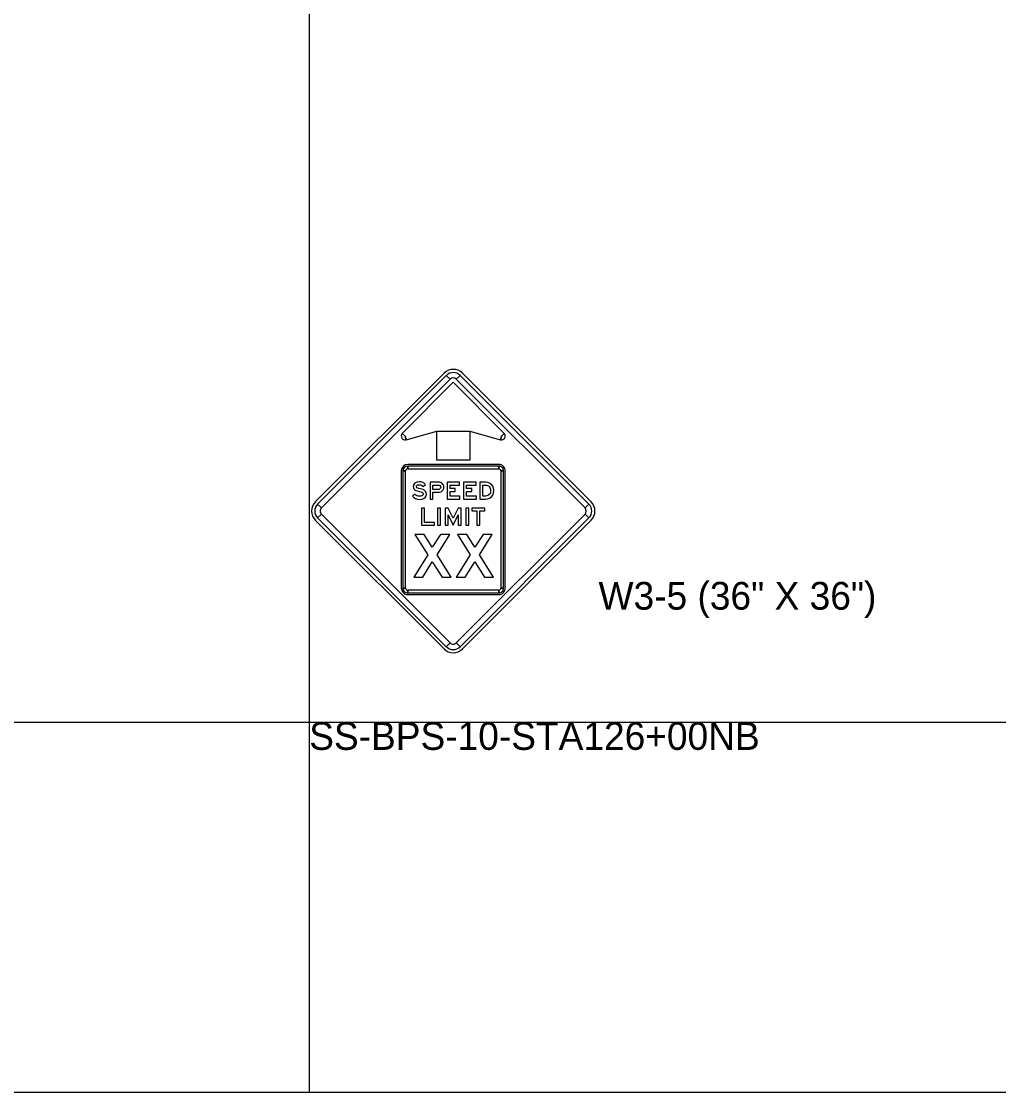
# Model space of a CAD drawing. Extents: x 1001568 to 1002149, y 1840825 to 1841423.
# Drawn here: x 1001900.5 to 1001914.59, y 1841048.13 to 1841063.57 of the extents above; entities that cross this region are included whole.
import ezdxf

# ---------------------------------------------------------------- set-up
doc = ezdxf.new("R2010")
doc.units = 0
for name, color, linetype in [('40', 7, 'Continuous'), ('R_No Plot', 7, 'Continuous'), ('SIGNS', 7, 'Continuous')]:
    doc.layers.add(name, color=color, linetype=linetype)

msp = doc.modelspace()

# ---------------------------------------------------------------- linework, layer by layer
at = {"layer": 'R_No Plot'}
for p, q in [((1001904.65, 1841110.667), (1001904.65, 1841048.127)), ((1001890.65, 1841053.469), (1001982.133, 1841053.469))]:
    msp.add_line(p, q, dxfattribs=at)
msp.add_lwpolyline([(1001886.411, 1841110.667), (1001964.232, 1841110.667), (1001964.232, 1841107.694), (1001968.454, 1841107.694), (1001968.454, 1841106.882), (1001982.133, 1841106.882), (1001982.133, 1841048.127), (1001886.411, 1841048.127)], close=True, dxfattribs=at)
at = {"layer": 'SIGNS'}
for p, q in [((1001906.594, 1841058.502), (1001904.738, 1841056.645)), ((1001906.627, 1841058.468), (1001906.683, 1841058.413)), ((1001906.771, 1841058.413), (1001906.826, 1841058.468)), ((1001908.716, 1841056.645), (1001906.859, 1841058.502)), ((1001906.032, 1841057.594), (1001905.992, 1841057.632)), ((1001906.046, 1841057.541), (1001906.032, 1841057.594)), ((1001907.422, 1841057.594), (1001907.408, 1841057.541)), ((1001907.462, 1841057.632), (1001907.422, 1841057.594)), ((1001905.977, 1841057.091), (1001905.977, 1841055.403)), ((1001906, 1841057.091), (1001906.039, 1841057.091)), ((1001907.383, 1841057.185), (1001906.071, 1841057.185)), ((1001906.071, 1841057.122), (1001906.071, 1841057.161)), ((1001907.383, 1841057.161), (1001907.383, 1841057.122)), ((1001907.414, 1841057.091), (1001907.453, 1841057.091)), ((1001907.477, 1841055.403), (1001907.477, 1841057.091)), ((1001904.827, 1841056.557), (1001904.771, 1841056.612)), ((1001908.682, 1841056.612), (1001908.627, 1841056.557)), ((1001904.771, 1841056.413), (1001904.827, 1841056.469)), ((1001908.627, 1841056.469), (1001908.682, 1841056.413)), ((1001904.738, 1841056.38), (1001906.594, 1841054.524)), ((1001906.859, 1841054.524), (1001908.716, 1841056.38)), ((1001906.039, 1841055.403), (1001906, 1841055.403)), ((1001906.071, 1841055.333), (1001906.071, 1841055.372)), ((1001907.383, 1841055.372), (1001907.383, 1841055.333)), ((1001907.453, 1841055.403), (1001907.414, 1841055.403)), ((1001906.071, 1841055.31), (1001907.383, 1841055.31)), ((1001906.683, 1841054.612), (1001906.627, 1841054.557)), ((1001906.826, 1841054.557), (1001906.771, 1841054.612))]:
    msp.add_line(p, q, dxfattribs=at)
for points in [[(1001906.627, 1841058.468), (1001904.771, 1841056.612), (1001904.827, 1841056.557), (1001906.683, 1841058.413), (1001906.627, 1841058.468), (1001906.627, 1841058.468)], [(1001908.682, 1841056.612), (1001906.826, 1841058.468), (1001906.771, 1841058.413), (1001908.627, 1841056.557), (1001908.682, 1841056.612), (1001908.682, 1841056.612)], [(1001906.727, 1841058.372), (1001905.992, 1841057.632), (1001906.032, 1841057.594), (1001906.046, 1841057.541), (1001906.489, 1841057.664), (1001906.965, 1841057.664), (1001907.408, 1841057.541), (1001907.422, 1841057.594), (1001907.462, 1841057.632), (1001906.727, 1841058.372), (1001906.727, 1841058.372)], [(1001906.965, 1841057.247), (1001906.489, 1841057.247), (1001906.489, 1841057.664), (1001906.965, 1841057.664), (1001906.965, 1841057.247), (1001906.965, 1841057.247)], [(1001906, 1841057.091), (1001906, 1841055.403), (1001906.039, 1841055.403), (1001906.039, 1841057.091), (1001906, 1841057.091), (1001906, 1841057.091)], [(1001907.383, 1841057.161), (1001906.071, 1841057.161), (1001906.071, 1841057.122), (1001907.383, 1841057.122), (1001907.383, 1841057.161), (1001907.383, 1841057.161)], [(1001907.453, 1841055.403), (1001907.453, 1841057.091), (1001907.414, 1841057.091), (1001907.414, 1841055.403), (1001907.453, 1841055.403), (1001907.453, 1841055.403)], [(1001906.139, 1841056.729), (1001906.161, 1841056.707), (1001906.185, 1841056.692), (1001906.212, 1841056.683), (1001906.242, 1841056.68), (1001906.277, 1841056.684), (1001906.307, 1841056.698), (1001906.321, 1841056.709), (1001906.331, 1841056.722), (1001906.338, 1841056.737), (1001906.34, 1841056.753), (1001906.337, 1841056.774), (1001906.33, 1841056.792), (1001906.318, 1841056.806), (1001906.302, 1841056.818), (1001906.278, 1841056.827), (1001906.232, 1841056.839), (1001906.216, 1841056.844), (1001906.204, 1841056.85), (1001906.197, 1841056.857), (1001906.195, 1841056.866), (1001906.197, 1841056.877), (1001906.205, 1841056.885), (1001906.218, 1841056.889), (1001906.236, 1841056.891), (1001906.253, 1841056.889), (1001906.268, 1841056.885), (1001906.282, 1841056.877), (1001906.295, 1841056.867), (1001906.329, 1841056.896), (1001906.309, 1841056.913), (1001906.287, 1841056.925), (1001906.264, 1841056.932), (1001906.238, 1841056.935), (1001906.205, 1841056.931), (1001906.178, 1841056.919), (1001906.166, 1841056.908), (1001906.157, 1841056.896), (1001906.152, 1841056.882), (1001906.15, 1841056.866), (1001906.153, 1841056.848), (1001906.16, 1841056.833), (1001906.171, 1841056.82), (1001906.188, 1841056.809), (1001906.258, 1841056.789), (1001906.274, 1841056.783), (1001906.286, 1841056.776), (1001906.293, 1841056.768), (1001906.295, 1841056.759), (1001906.294, 1841056.751), (1001906.29, 1841056.744), (1001906.284, 1841056.738), (1001906.276, 1841056.733), (1001906.259, 1841056.727), (1001906.241, 1841056.726), (1001906.222, 1841056.728), (1001906.204, 1841056.734), (1001906.189, 1841056.744), (1001906.175, 1841056.758)], [(1001906.637, 1841056.685), (1001906.822, 1841056.685), (1001906.822, 1841056.728), (1001906.682, 1841056.728), (1001906.682, 1841056.795), (1001906.756, 1841056.795), (1001906.756, 1841056.838), (1001906.682, 1841056.838), (1001906.682, 1841056.887), (1001906.818, 1841056.887), (1001906.818, 1841056.93), (1001906.637, 1841056.93)], [(1001906.874, 1841056.685), (1001907.06, 1841056.685), (1001907.06, 1841056.728), (1001906.919, 1841056.728), (1001906.919, 1841056.795), (1001906.994, 1841056.795), (1001906.994, 1841056.838), (1001906.919, 1841056.838), (1001906.919, 1841056.887), (1001907.056, 1841056.887), (1001907.056, 1841056.93), (1001906.874, 1841056.93)], [(1001904.771, 1841056.413), (1001906.627, 1841054.557), (1001906.683, 1841054.612), (1001904.827, 1841056.469), (1001904.771, 1841056.413), (1001904.771, 1841056.413)], [(1001906.269, 1841056.31), (1001906.455, 1841056.31), (1001906.455, 1841056.347), (1001906.313, 1841056.347), (1001906.313, 1841056.555), (1001906.269, 1841056.555)], [(1001906.499, 1841056.31), (1001906.544, 1841056.31), (1001906.544, 1841056.555), (1001906.499, 1841056.555)], [(1001906.609, 1841056.31), (1001906.653, 1841056.31), (1001906.653, 1841056.46), (1001906.725, 1841056.31), (1001906.798, 1841056.46), (1001906.798, 1841056.31), (1001906.842, 1841056.31), (1001906.842, 1841056.555), (1001906.798, 1841056.555), (1001906.725, 1841056.41), (1001906.652, 1841056.555), (1001906.609, 1841056.555)], [(1001906.826, 1841054.557), (1001908.682, 1841056.413), (1001908.627, 1841056.469), (1001906.771, 1841054.612), (1001906.826, 1841054.557), (1001906.826, 1841054.557)], [(1001906.909, 1841056.31), (1001906.954, 1841056.31), (1001906.954, 1841056.555), (1001906.909, 1841056.555)], [(1001907.068, 1841056.31), (1001907.111, 1841056.31), (1001907.111, 1841056.514), (1001907.182, 1841056.514), (1001907.182, 1841056.555), (1001906.997, 1841056.555), (1001906.997, 1841056.514), (1001907.068, 1841056.514)], [(1001906.158, 1841055.56), (1001906.288, 1841055.56), (1001906.425, 1841055.78), (1001906.565, 1841055.56), (1001906.696, 1841055.56), (1001906.493, 1841055.883), (1001906.676, 1841056.173), (1001906.543, 1841056.173), (1001906.425, 1841055.99), (1001906.308, 1841056.173), (1001906.175, 1841056.173), (1001906.36, 1841055.883)], [(1001906.771, 1841055.56), (1001906.901, 1841055.56), (1001907.039, 1841055.78), (1001907.178, 1841055.56), (1001907.309, 1841055.56), (1001907.106, 1841055.883), (1001907.289, 1841056.173), (1001907.156, 1841056.173), (1001907.039, 1841055.99), (1001906.921, 1841056.173), (1001906.788, 1841056.173), (1001906.973, 1841055.883)], [(1001906.071, 1841055.333), (1001907.383, 1841055.333), (1001907.383, 1841055.372), (1001906.071, 1841055.372), (1001906.071, 1841055.333), (1001906.071, 1841055.333)]]:
    msp.add_lwpolyline(points, close=True, dxfattribs=at)
for points in [[(1001906.392, 1841056.685), (1001906.435, 1841056.685), (1001906.435, 1841056.783), (1001906.507, 1841056.783), (1001906.531, 1841056.785), (1001906.552, 1841056.792), (1001906.568, 1841056.803), (1001906.581, 1841056.819), (1001906.589, 1841056.837), (1001906.592, 1841056.856), (1001906.591, 1841056.872), (1001906.586, 1841056.886), (1001906.579, 1841056.898), (1001906.569, 1841056.909), (1001906.557, 1841056.918), (1001906.543, 1841056.925), (1001906.528, 1841056.928), (1001906.512, 1841056.93), (1001906.392, 1841056.93), (1001906.392, 1841056.685)], [(1001907.112, 1841056.685), (1001907.193, 1841056.685), (1001907.223, 1841056.688), (1001907.252, 1841056.7), (1001907.278, 1841056.719), (1001907.297, 1841056.744), (1001907.308, 1841056.774), (1001907.312, 1841056.808), (1001907.308, 1841056.842), (1001907.297, 1841056.871), (1001907.278, 1841056.895), (1001907.252, 1841056.914), (1001907.224, 1841056.926), (1001907.195, 1841056.93), (1001907.112, 1841056.93), (1001907.112, 1841056.685)], [(1001906.435, 1841056.824), (1001906.435, 1841056.887), (1001906.508, 1841056.887), (1001906.523, 1841056.885), (1001906.534, 1841056.879), (1001906.543, 1841056.868), (1001906.546, 1841056.855), (1001906.543, 1841056.842), (1001906.535, 1841056.833), (1001906.524, 1841056.826), (1001906.51, 1841056.824), (1001906.435, 1841056.824)], [(1001907.155, 1841056.728), (1001907.155, 1841056.888), (1001907.191, 1841056.888), (1001907.207, 1841056.886), (1001907.222, 1841056.882), (1001907.235, 1841056.875), (1001907.246, 1841056.865), (1001907.255, 1841056.854), (1001907.261, 1841056.84), (1001907.264, 1841056.826), (1001907.266, 1841056.809), (1001907.264, 1841056.786), (1001907.257, 1841056.768), (1001907.245, 1841056.753), (1001907.227, 1841056.739), (1001907.208, 1841056.731), (1001907.191, 1841056.728), (1001907.155, 1841056.728)]]:
    msp.add_lwpolyline(points, dxfattribs=at)
for centre, radius, start, end in [((1001906.727, 1841058.369), 0.187, 45, 134.9997), ((1001906.727, 1841058.369), 0.141, 45, 134.9997), ((1001906.727, 1841058.369), 0.0625, 45, 134.9997), ((1001906.032, 1841057.594), 0.0547, 136.148, 285.5381), ((1001907.422, 1841057.594), 0.0547, 254.462, 43.8522), ((1001906.071, 1841057.091), 0.0937, 90.0002, 179.9998), ((1001906.071, 1841057.091), 0.0703, 90.0002, 179.9998), ((1001906.071, 1841057.091), 0.0312, 90.0002, 179.9998), ((1001907.383, 1841057.091), 0.0937, 0, 90.0002), ((1001907.383, 1841057.091), 0.0703, 0, 90.0002), ((1001907.383, 1841057.091), 0.0312, 0, 90.0002), ((1001904.871, 1841056.513), 0.187, 134.9997, 225), ((1001904.871, 1841056.513), 0.141, 134.9997, 225), ((1001908.583, 1841056.513), 0.141, 315.0002, 44.9998), ((1001908.583, 1841056.513), 0.187, 315.0002, 44.9998), ((1001904.871, 1841056.513), 0.0625, 134.9997, 225), ((1001908.583, 1841056.513), 0.0625, 315.0002, 44.9998), ((1001906.071, 1841055.403), 0.0937, 179.9998, 270.0001), ((1001906.071, 1841055.403), 0.0703, 179.9998, 270.0001), ((1001906.071, 1841055.403), 0.0312, 179.9998, 270.0001), ((1001907.383, 1841055.403), 0.0937, 270.0001, 0.0003), ((1001907.383, 1841055.403), 0.0703, 270.0001, 0.0003), ((1001907.383, 1841055.403), 0.0312, 270.0001, 0.0003), ((1001906.727, 1841054.657), 0.0625, 225, 315.0002), ((1001906.727, 1841054.657), 0.187, 225, 315.0002), ((1001906.727, 1841054.657), 0.141, 225, 315.0002)]:
    msp.add_arc(centre, radius, start, end, dxfattribs=at)

# ---------------------------------------------------------------- texts
at = {"layer": '40'}
for s, p in [('W3-5 (36" X 36")', (1001908.822, 1841055.091)), ('SS-BPS-10-STA126+00NB', (1001904.65, 1841053.069))]:
    msp.add_text(s, height=0.4, rotation=0, dxfattribs=at).set_placement(p)

doc.saveas('drawing.dxf')
